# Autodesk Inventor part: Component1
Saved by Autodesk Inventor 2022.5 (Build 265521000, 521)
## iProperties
Created: 2024-12
Part Number: Component1
Material: Generic
Document SubType Name: Modeling
Designer: AdminForWorker
Density: 1 g/cm^3
Appearance: Default
Title: Component1
Author: AdminForWorker
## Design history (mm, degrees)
feature "Body1"
body "Solid1"
